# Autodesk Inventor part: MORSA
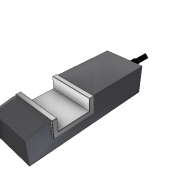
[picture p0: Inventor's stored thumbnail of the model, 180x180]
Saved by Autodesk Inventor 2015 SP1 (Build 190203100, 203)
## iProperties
Created: 2014-10
Part Number: MORSA
Material: Generic
Document SubType Name: Modeling
Designer: Guilherme Augusto
Density: 1 g/cm^3
Appearance: Default
Author: Guilherme Augusto
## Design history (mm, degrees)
sketch "Sketch1"
  geometry: L1 (-40, 32)-(-40, 0); L2 (-40, 0)-(40, 0); L3 (40, 0)-(40, 32); L4 (40, 32)-(52, 32); L5 (52, 32)-(52, -12); L6 (52, -12)-(-52, -12); L7 (-52, -12)-(-52, 32); L8 (-52, 32)-(-40, 32); 2 further points
  constraints: 16 end point, 6 perpendicular, 1 coincident, 1 collinear, 1 horizontal, 1 midpoint, 1 point on line, 1 vertical
  dimensions: "d0" = 12 distance of L1.start L7.end; "d1" = 32 distance of L1.start L1.end; "d2" = 12 distance between parallel lines of L2 L6 (= d0); "d3" = 80 distance between parallel lines of L1 L3
extrude "Extrusion1" new body sketch "Sketch1" stored distance "d4" = 113; taper "d5" = 0 deg
sketch "Sketch2"
  geometry: L1 (-52, -12)-(-52, 32) reference; L2 (52, 32)-(52, -12) reference; L3 (52, -12)-(-52, -12) reference; L4 (-52, 31)-(-62, 31); L5 (-62, 31)-(-107, 21); L6 (-107, 21)-(-107, -42); L7 (-107, -42)-(212, -42); L8 (212, -42)-(212, 31); L9 (212, 31)-(52, 31); L10 (52, -12)-(52, 31); L11 (-52, 31)-(-52, -12); 1 further point
  constraints: 16 end point, 4 perpendicular, 3 point on line, 2 collinear, 1 horizontal
  dimensions: "d9" = 160 distance of L8.end L9.end; "d10" = 55 distance between parallel lines of L6 L1; "d11" = 10 distance of L4.start L4.end; "d12" = 30 distance between parallel lines of L3 L7; "d13" = 10 vertical distance of L4.end L5.end; "d14" = 1 distance from line of L1.end L4
extrude "Extrusion2" join sketch "Sketch2" stored distance "d15" = 106; taper "d16" = 0 deg
sketch "Sketch3"
  geometry: C1 r 10 at (53, 42); 1 further point
  constraints: 1 centre point, 1 coincident
  dimensions: "d17" = 20 diameter of C1
extrude "Extrusion3" join sketch "Sketch3" distance "d18" = 50; taper "d19" = 0 deg
sketch "Sketch4"
  geometry: L1 (0, 10)-(10, 0); L2 (10, 0)-(0, -10); L3 (0, -10)-(-10, 0); L4 (-10, 0)-(0, 10); 2 further points
  constraints: 8 end point, 1 coincident, 1 vertical alignment, 9 other
  dimensions: "d21" = 20 distance of L2.end L1.start
extrude "Extrusion4" join sketch "Sketch4" distance "d22" = 40; taper "d23" = 0 deg
chamfer "Chamfer1" distance "d6" = 1; stored, may be unused: second distance "d7" = 2, angle "d8" = 45 deg
body "Solid1"
